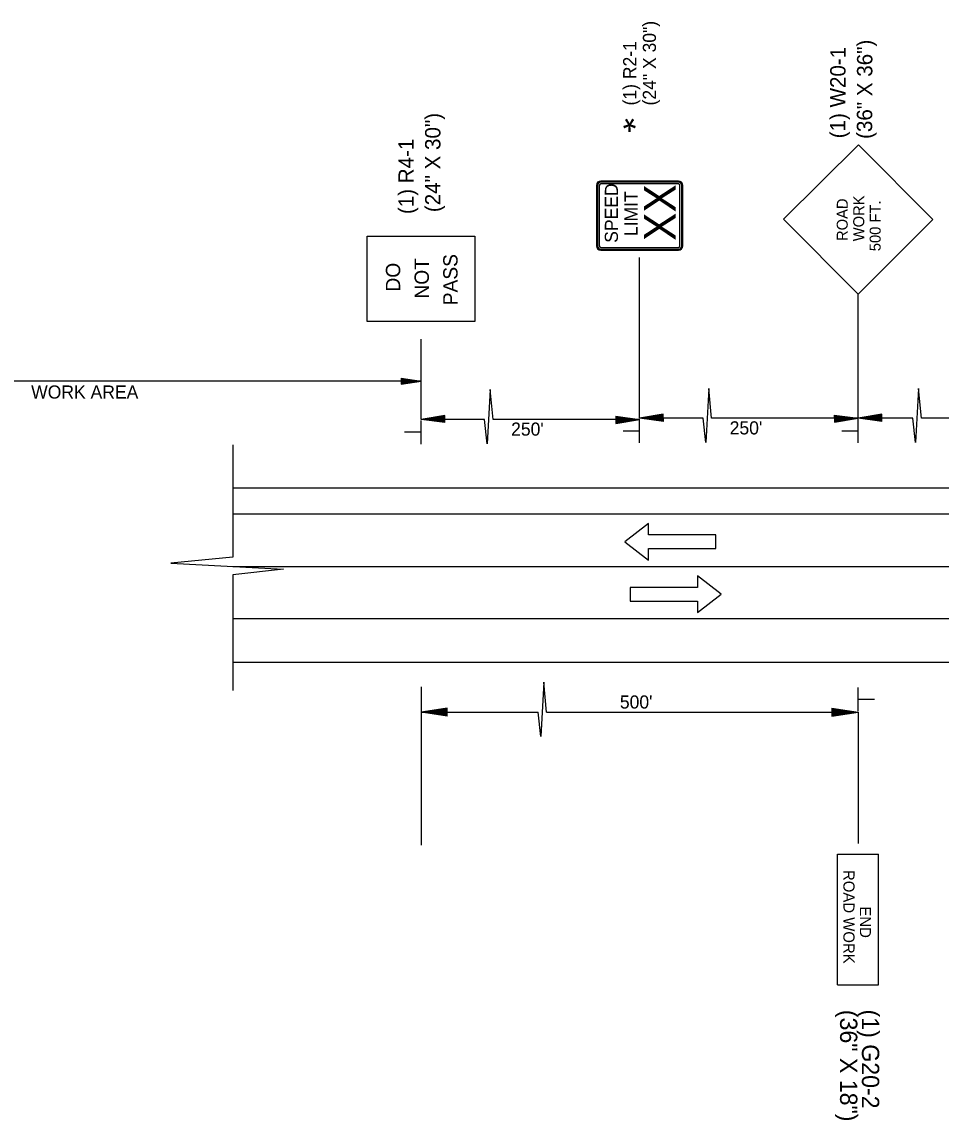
# Model space of a CAD drawing. Extents: x -160 to 6143532, y -375 to 762199.
# Drawn here: x -92.47 to -54.93, y 53.02 to 97.85 of the extents above; entities that cross this region are included whole.
import ezdxf

# ---------------------------------------------------------------- set-up
doc = ezdxf.new("R2010")
doc.units = 0
for name, color, linetype in [('Level 3', 7, 'Continuous'), ('Level 42', 7, 'Continuous'), ('Level 8', 7, 'Continuous'), ('P_TC_Signs_Permanent', 7, 'Continuous'), ('R_Annotation', 7, 'Continuous'), ('R_Centerline', 7, 'Continuous'), ('R_Dimension', 7, 'Continuous'), ('R_Draft', 7, 'Continuous'), ('R_Striping', 7, 'Continuous')]:
    doc.layers.add(name, color=color, linetype=linetype)

msp = doc.modelspace()

# ---------------------------------------------------------------- linework, layer by layer
at = {"layer": 'Level 3'}
for p, q in [((-67.241, 80.67), (-67.241, 81.634)), ((-58.314, 80.67), (-58.314, 81.634)), ((-76.167, 80.621), (-76.167, 81.585)), ((-76.181, 81.1), (-76.839, 81.1)), ((-67.255, 81.15), (-67.913, 81.15)), ((-58.328, 81.15), (-58.986, 81.15)), ((-58.314, 69.718), (-58.314, 70.682)), ((-58.3, 70.197), (-57.642, 70.197))]:
    msp.add_line(p, q, dxfattribs=at)
at = {"layer": 'Level 42'}
for p, q in [((-59.153, 58.536), (-59.154, 63.875)), ((-59.154, 63.875), (-57.476, 63.875)), ((-57.476, 58.537), (-57.476, 63.875)), ((-59.153, 58.536), (-57.476, 58.537))]:
    msp.add_line(p, q, dxfattribs=at)
at = {"layer": 'Level 8'}
for p, q in [((-58.296, 92.841), (-61.356, 89.799)), ((-58.296, 92.841), (-55.257, 89.781)), ((-61.356, 89.799), (-58.314, 86.739)), ((-55.257, 89.781), (-58.314, 86.739))]:
    msp.add_line(p, q, dxfattribs=at)
msp.add_lwpolyline([(-78.367, 89.112), (-73.965, 89.112), (-73.965, 85.619), (-78.367, 85.619)], close=True, dxfattribs=at)
at = {"layer": 'P_TC_Signs_Permanent'}
for p, q in [((-69.006, 91.181), (-69.006, 88.709)), ((-68.961, 91.181), (-68.961, 88.709)), ((-68.888, 91.181), (-68.888, 88.709)), ((-65.651, 91.357), (-68.829, 91.357)), ((-65.651, 91.313), (-68.829, 91.313)), ((-65.651, 91.239), (-68.829, 91.239)), ((-65.592, 88.709), (-65.592, 91.181)), ((-65.519, 88.709), (-65.519, 91.181)), ((-65.475, 88.709), (-65.475, 91.181)), ((-68.829, 88.65), (-65.651, 88.65)), ((-68.829, 88.577), (-65.651, 88.577)), ((-68.829, 88.532), (-65.651, 88.532))]:
    msp.add_line(p, q, dxfattribs=at)
for centre, radius, start, end in [((-68.829, 91.181), 0.177, 90, 180), ((-68.829, 91.181), 0.132, 90, 180), ((-68.829, 91.181), 0.0588, 90, 180), ((-65.651, 91.181), 0.177, 360, 90), ((-65.651, 91.181), 0.132, 360, 90), ((-65.651, 91.181), 0.0588, 360, 90), ((-68.829, 88.709), 0.177, 180, 270), ((-68.829, 88.709), 0.132, 180, 270), ((-68.829, 88.709), 0.0588, 180, 270), ((-65.651, 88.709), 0.177, 270, 360), ((-65.651, 88.709), 0.132, 270, 360), ((-65.651, 88.709), 0.0588, 270, 360)]:
    msp.add_arc(centre, radius, start, end, dxfattribs=at)
at = {"layer": 'R_Centerline'}
msp.add_line((-83.854, 75.619), (-22.609, 75.619), dxfattribs=at)
at = {"layer": 'R_Dimension'}
for p, q in [((-67.24, 81.674), (-67.24, 88.23)), ((-58.314, 81.674), (-58.314, 86.739)), ((-76.166, 81.625), (-76.166, 84.903)), ((-76.166, 83.188), (-97.318, 83.188)), ((-76.976, 83.31), (-76.166, 83.188)), ((-76.976, 83.31), (-76.976, 83.067)), ((-76.976, 83.289), (-76.302, 83.188)), ((-76.976, 83.269), (-76.441, 83.188)), ((-76.976, 83.249), (-76.575, 83.188)), ((-76.976, 83.227), (-76.713, 83.188)), ((-76.976, 83.207), (-76.848, 83.188)), ((-76.976, 83.067), (-76.166, 83.188)), ((-76.976, 83.149), (-76.713, 83.188)), ((-76.976, 83.108), (-76.441, 83.188)), ((-76.976, 83.087), (-76.302, 83.188)), ((-76.976, 83.128), (-76.575, 83.188)), ((-76.976, 83.169), (-76.848, 83.188)), ((-75.198, 81.786), (-76.166, 81.625)), ((-75.193, 81.495), (-76.166, 81.625)), ((-73.572, 81.625), (-76.166, 81.625)), ((-75.197, 81.762), (-76.004, 81.628)), ((-75.193, 81.519), (-76.004, 81.628)), ((-75.197, 81.737), (-75.837, 81.63)), ((-75.194, 81.544), (-75.837, 81.63)), ((-75.196, 81.713), (-75.675, 81.633)), ((-75.194, 81.568), (-75.675, 81.633)), ((-75.196, 81.688), (-75.511, 81.636)), ((-75.195, 81.593), (-75.511, 81.636)), ((-75.195, 81.663), (-75.348, 81.638)), ((-75.195, 81.618), (-75.348, 81.638)), ((-75.193, 81.495), (-75.198, 81.786)), ((-67.24, 81.625), (-73.225, 81.625)), ((-68.213, 81.755), (-67.24, 81.625)), ((-68.213, 81.755), (-68.209, 81.464)), ((-68.213, 81.731), (-67.402, 81.622)), ((-68.213, 81.706), (-67.569, 81.62)), ((-68.212, 81.682), (-67.731, 81.617)), ((-68.212, 81.657), (-67.896, 81.614)), ((-68.211, 81.632), (-68.058, 81.612)), ((-68.211, 81.562), (-67.896, 81.614)), ((-68.211, 81.587), (-68.058, 81.612)), ((-68.21, 81.513), (-67.569, 81.62)), ((-68.21, 81.537), (-67.731, 81.617)), ((-68.209, 81.464), (-67.24, 81.625)), ((-68.209, 81.488), (-67.402, 81.622)), ((-66.271, 81.836), (-67.24, 81.674)), ((-66.267, 81.544), (-67.24, 81.674)), ((-64.646, 81.674), (-67.24, 81.674)), ((-66.271, 81.811), (-67.078, 81.677)), ((-66.267, 81.568), (-67.078, 81.677)), ((-66.27, 81.786), (-66.911, 81.68)), ((-66.268, 81.593), (-66.911, 81.68)), ((-66.27, 81.762), (-66.749, 81.682)), ((-66.268, 81.618), (-66.749, 81.682)), ((-66.27, 81.737), (-66.585, 81.685)), ((-66.268, 81.643), (-66.585, 81.685)), ((-66.269, 81.713), (-66.422, 81.688)), ((-66.268, 81.667), (-66.422, 81.688)), ((-66.267, 81.544), (-66.271, 81.836)), ((-58.314, 81.674), (-64.299, 81.674)), ((-59.287, 81.804), (-58.314, 81.674)), ((-59.287, 81.804), (-59.283, 81.513)), ((-59.287, 81.78), (-58.476, 81.672)), ((-59.286, 81.755), (-58.643, 81.669)), ((-59.286, 81.731), (-58.805, 81.666)), ((-59.286, 81.706), (-58.97, 81.664)), ((-59.285, 81.682), (-59.131, 81.661)), ((-59.285, 81.636), (-59.131, 81.661)), ((-59.284, 81.562), (-58.643, 81.669)), ((-59.284, 81.586), (-58.805, 81.666)), ((-59.284, 81.611), (-58.97, 81.664)), ((-59.283, 81.513), (-58.314, 81.674)), ((-59.283, 81.537), (-58.476, 81.672)), ((-57.345, 81.836), (-58.314, 81.674)), ((-57.341, 81.544), (-58.314, 81.674)), ((-56.074, 81.674), (-58.314, 81.674)), ((-57.345, 81.811), (-58.152, 81.677)), ((-57.341, 81.568), (-58.152, 81.677)), ((-57.344, 81.786), (-57.985, 81.68)), ((-57.341, 81.593), (-57.985, 81.68)), ((-57.344, 81.762), (-57.823, 81.682)), ((-57.342, 81.618), (-57.823, 81.682)), ((-57.343, 81.737), (-57.658, 81.685)), ((-57.342, 81.643), (-57.658, 81.685)), ((-57.343, 81.713), (-57.496, 81.688)), ((-57.342, 81.667), (-57.496, 81.688)), ((-57.341, 81.544), (-57.345, 81.836)), ((-49.388, 81.674), (-55.727, 81.674)), ((-76.166, 70.702), (-76.166, 64.248)), ((-75.098, 69.833), (-76.166, 69.673)), ((-76.166, 69.673), (-71.387, 69.673)), ((-75.098, 69.512), (-76.166, 69.673)), ((-75.098, 69.806), (-75.988, 69.673)), ((-75.098, 69.539), (-75.988, 69.673)), ((-75.098, 69.779), (-75.804, 69.673)), ((-75.098, 69.566), (-75.804, 69.673)), ((-75.098, 69.752), (-75.626, 69.673)), ((-75.098, 69.593), (-75.626, 69.673)), ((-75.098, 69.725), (-75.445, 69.673)), ((-75.098, 69.621), (-75.445, 69.673)), ((-75.098, 69.698), (-75.267, 69.673)), ((-75.098, 69.648), (-75.267, 69.673)), ((-75.098, 69.512), (-75.098, 69.833)), ((-71.04, 69.673), (-58.314, 69.673)), ((-59.382, 69.833), (-58.314, 69.673)), ((-59.382, 69.833), (-59.382, 69.512)), ((-59.382, 69.806), (-58.492, 69.673)), ((-59.382, 69.779), (-58.676, 69.673)), ((-59.382, 69.752), (-58.854, 69.673)), ((-59.382, 69.725), (-59.035, 69.673)), ((-59.382, 69.698), (-59.214, 69.673)), ((-59.382, 69.512), (-58.314, 69.673)), ((-59.382, 69.621), (-59.035, 69.673)), ((-59.382, 69.566), (-58.676, 69.673)), ((-59.382, 69.539), (-58.492, 69.673)), ((-59.382, 69.593), (-58.854, 69.673)), ((-59.382, 69.648), (-59.214, 69.673)), ((-58.315, 69.673), (-58.315, 64.311))]:
    msp.add_line(p, q, dxfattribs=at)
for points in [[(-73.225, 81.625), (-73.342, 82.844), (-73.464, 80.632)], [(-64.299, 81.674), (-64.416, 82.893), (-64.538, 80.681)], [(-55.727, 81.674), (-55.844, 82.893), (-55.966, 80.681)], [(-73.464, 80.632), (-73.572, 81.625)], [(-64.538, 80.681), (-64.646, 81.674)], [(-55.966, 80.681), (-56.074, 81.674)], [(-83.85, 80.592), (-83.85, 76.001), (-86.381, 75.758), (-81.787, 75.505)], [(-81.787, 75.505), (-83.85, 75.281), (-83.85, 70.563)], [(-71.04, 69.673), (-71.157, 70.892), (-71.278, 68.679)], [(-71.278, 68.679), (-71.387, 69.673)]]:
    msp.add_lwpolyline(points, dxfattribs=at)
at = {"layer": 'R_Draft'}
for p, q in [((-75.198, 81.786), (-76.166, 81.625)), ((-75.193, 81.495), (-76.166, 81.625)), ((-75.197, 81.762), (-76.004, 81.628)), ((-75.193, 81.519), (-76.004, 81.628)), ((-75.197, 81.737), (-75.837, 81.63)), ((-75.194, 81.544), (-75.837, 81.63)), ((-75.196, 81.713), (-75.675, 81.633)), ((-75.194, 81.568), (-75.675, 81.633)), ((-75.196, 81.688), (-75.511, 81.636)), ((-75.195, 81.593), (-75.511, 81.636)), ((-75.195, 81.663), (-75.349, 81.638)), ((-75.195, 81.618), (-75.349, 81.638)), ((-75.193, 81.495), (-75.198, 81.786)), ((-66.271, 81.836), (-67.24, 81.674)), ((-66.267, 81.544), (-67.24, 81.674)), ((-66.271, 81.812), (-67.078, 81.677)), ((-66.267, 81.569), (-67.078, 81.677)), ((-66.27, 81.786), (-66.911, 81.68)), ((-66.268, 81.593), (-66.911, 81.68)), ((-66.27, 81.763), (-66.749, 81.682)), ((-66.268, 81.618), (-66.749, 81.682)), ((-66.27, 81.737), (-66.585, 81.685)), ((-66.268, 81.643), (-66.585, 81.685)), ((-66.269, 81.713), (-66.423, 81.688)), ((-66.269, 81.667), (-66.423, 81.688)), ((-66.267, 81.544), (-66.271, 81.836)), ((-22.609, 78.824), (-83.854, 78.824)), ((-22.609, 77.756), (-83.854, 77.756)), ((-22.609, 73.482), (-83.854, 73.482)), ((-22.609, 71.701), (-83.854, 71.701))]:
    msp.add_line(p, q, dxfattribs=at)
at = {"layer": 'R_Striping'}
for points in [[(-66.875, 77.377), (-67.847, 76.629), (-66.875, 75.88), (-66.875, 76.348), (-64.121, 76.348), (-64.121, 76.909), (-66.875, 76.909)], [(-64.873, 73.737), (-63.902, 74.486), (-64.873, 75.234), (-64.873, 74.766), (-67.627, 74.766), (-67.627, 74.205), (-64.873, 74.205)]]:
    msp.add_lwpolyline(points, close=True, dxfattribs=at)

# ---------------------------------------------------------------- texts
at = {"layer": 'Level 42'}
for s, p in [('ROAD WORK', (-58.917, 63.229)), ('END', (-58.244, 61.742))]:
    msp.add_text(s, height=0.4558, rotation=270.0014, dxfattribs=at).set_placement(p)
at = {"layer": 'Level 8'}
for s, height, rotation, p in [('(36" X 36")', 0.62813, 89.8307, (-57.742, 93.077)), ('(1) W20-1', 0.6281, 89.8307, (-58.835, 93.103)), ('(24" X 30")', 0.62813, 90, (-75.374, 90.088)), ('(1) R4-1', 0.6281, 90, (-76.462, 90.009)), ('SPEED ', 0.5357, 90, (-68.125, 88.836)), ('XX', 1.2976, 90, (-65.761, 88.912)), ('LIMIT', 0.5357, 90, (-67.322, 89.11)), ('ROAD', 0.4495, 89.8312, (-58.742, 88.91)), ('WORK', 0.4494, 89.8307, (-58.068, 88.899)), ('500 FT. ', 0.4495, 89.8313, (-57.396, 88.493)), ('PASS', 0.5859, 90, (-74.675, 86.286)), ('DO', 0.5859, 90, (-77.018, 86.845)), ('NOT', 0.5859, 90, (-75.847, 86.558)), ('(36" X 18")', 0.70664, 270.0014, (-59.053, 57.518)), ('(1) G20-2', 0.7066, 270.0014, (-58.16, 57.53))]:
    msp.add_text(s, height=height, rotation=rotation, dxfattribs=at).set_placement(p)
at = {"layer": 'R_Annotation'}
for s, height, rotation, p in [('(24" X 30")', 0.53557, 90, (-66.572, 94.443)), ('(1) R2-1', 0.5356, 90, (-67.376, 94.443)), ('*', 1.071, 180, (-67.373, 94.433)), ("250'", 0.5356, 360, (-72.488, 80.962)), ("250'", 0.5356, 360, (-63.561, 81.012)), ("500'", 0.5356, 360, (-68.046, 69.82))]:
    msp.add_text(s, height=height, rotation=rotation, dxfattribs=at).set_placement(p)
msp.add_text('WORK AREA', height=0.5356, dxfattribs=at).set_placement((-92.091, 82.476))

doc.saveas('drawing.dxf')
